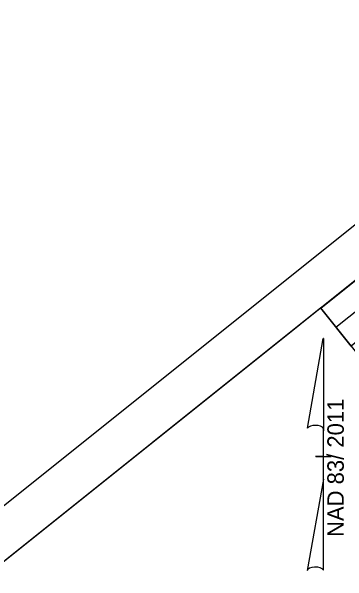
# Model space of a CAD drawing. Extents: x 473546 to 475544, y 505920 to 507827.
# Drawn here: x 474545 to 474718.5, y 507532.4 to 507826.8 of the extents above; entities that cross this region are included whole.
import ezdxf

# ---------------------------------------------------------------- set-up
doc = ezdxf.new("R2010")
doc.units = 0
for name, color, linetype in [('Prop North Arrow NAD83 for Plan Sheets CELL', 7, 'Continuous'), ('Sheet Clip Boundary CELL', 7, 'Continuous'), ('Sheet Plan CELL', 7, 'Continuous'), ('Sheet Plot Border Outside CELL', 7, 'Continuous')]:
    doc.layers.add(name, color=color, linetype=linetype)

msp = doc.modelspace()

# ---------------------------------------------------------------- linework, layer by layer
at = {"layer": 'Prop North Arrow NAD83 for Plan Sheets CELL'}
for p, q in [((474697.79, 507611.62), (474705.99, 507657.97)), ((474706.04, 507657.97), (474705.99, 507657.97)), ((474706.04, 507657.97), (474705.99, 507657.97)), ((474706.04, 507657.97), (474706.04, 507610.17)), ((474706.04, 507585.37), (474706.04, 507611.57)), ((474706.04, 507610.17), (474706.04, 507611.52)), ((474702.04, 507596.97), (474701.99, 507596.97)), ((474705.59, 507596.97), (474702.04, 507596.97)), ((474702.09, 507596.97), (474710.09, 507596.97)), ((474706.04, 507585.37), (474697.69, 507538.12)), ((474706.09, 507538.32), (474706.04, 507585.37))]:
    msp.add_line(p, q, dxfattribs=at)
for centre, start_param, end_param in [((474701.92, 507611.12), 0.216388, 2.908219), ((474701.92, 507537.95), 0.201328, 3.141593)]:
    msp.add_ellipse(centre, major_axis=(4.23, -0.03), ratio=0.461098, start_param=start_param, end_param=end_param, dxfattribs=at)
at = {"layer": 'Sheet Clip Boundary CELL'}
msp.add_lwpolyline([(474813.14, 507538.12), (474704.64, 507673.67), (473746.99, 506907.14), (474401.7, 506086.25), (475384.17, 506871.79), (475333.84, 506934.75), (475466.73, 507041), (474969.31, 507663.12)], close=True, dxfattribs=at)
at = {"layer": 'Sheet Plan CELL'}
msp.add_line((474712.51, 507663.81), (474868.71, 507788.81), dxfattribs=at)
for points in [[(474860.89, 507798.63), (473689.75, 506861.33), (474345.84, 506041.55), (475516.97, 506978.83)], [(474704.68, 507673.62), (474860.89, 507798.63), (474876.52, 507779.05), (474720.35, 507654.03)]]:
    msp.add_lwpolyline(points, close=True, dxfattribs=at)
at = {"layer": 'Sheet Plot Border Outside CELL'}
msp.add_lwpolyline([(474229.92, 505919.94), (475544.31, 506971.88), (474860.1, 507826.79), (473545.71, 506774.86)], close=True, dxfattribs=at)

# ---------------------------------------------------------------- texts
at = {"layer": 'Prop North Arrow NAD83 for Plan Sheets CELL'}
msp.add_text('NAD 83/ 2011', height=8.5, rotation=90, dxfattribs=at).set_placement((474716.56, 507555.45))

doc.saveas('drawing.dxf')
